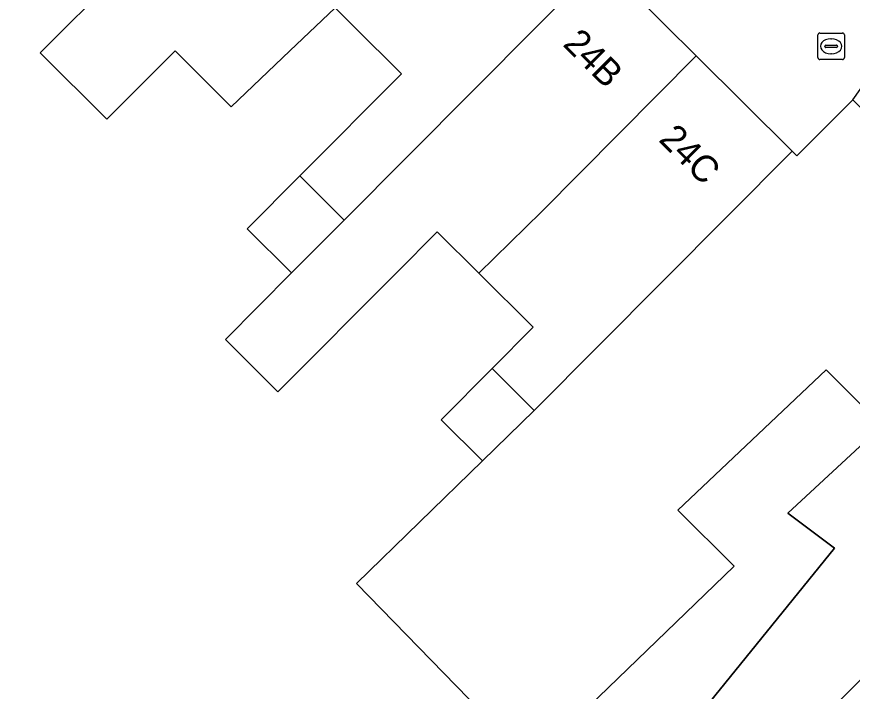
# Model space of a CAD drawing. Extents: x 160102 to 160934, y 382045 to 382923.
# Drawn here: x 160735.02 to 160766.51, y 382716.72 to 382742.13 of the extents above; entities that cross this region are included whole.
import ezdxf

# ---------------------------------------------------------------- set-up
doc = ezdxf.new("R2010")
doc.units = 0
for name, color, linetype in [('IMGEO_Brandkraan', 7, 'Continuous'), ('IMGEO_Erf', 7, 'Continuous'), ('IMGEO_Pand', 7, 'Continuous'), ('IMGEO_Pand_nummerreeks', 7, 'Continuous'), ('IMGEO_Voetpad_open', 7, 'Continuous')]:
    doc.layers.add(name, color=color, linetype=linetype)

msp = doc.modelspace()

# ---------------------------------------------------------------- linework, layer by layer
at = {"layer": 'IMGEO_Brandkraan'}
for p, q in [((160765.209, 382740.594), (160765.209, 382741.446)), ((160765.284, 382741.52), (160766.136, 382741.52)), ((160766.21, 382741.446), (160766.21, 382740.594)), ((160765.468, 382741.014), (160765.468, 382741.026)), ((160765.511, 382741.063), (160765.909, 382741.063)), ((160765.697, 382741.3), (160765.722, 382741.3)), ((160765.952, 382741.026), (160765.952, 382741.014)), ((160765.906, 382740.977), (160765.508, 382740.977)), ((160765.72, 382740.74), (160765.695, 382740.74)), ((160766.136, 382740.52), (160765.284, 382740.52))]:
    msp.add_line(p, q, dxfattribs=at)
for points in [[(160765.209, 382740.594), (160765.209, 382741.446)], [(160765.284, 382741.52), (160766.136, 382741.52)], [(160766.21, 382741.446), (160766.21, 382740.594)], [(160766.136, 382740.52), (160765.284, 382740.52)]]:
    msp.add_lwpolyline(points, dxfattribs=at)
for centre, radius, start, end in [((160765.286, 382741.444), 0.0765, 91.552, 178.448), ((160765.286, 382741.444), 0.0765, 91.552, 178.448), ((160766.134, 382741.444), 0.0765, 1.552, 88.448), ((160766.134, 382741.444), 0.0765, 1.552, 88.448), ((160765.508, 382741.023), 0.0403, 85.8775, 175.7526), ((160765.505, 382741.013), 0.0366, 178.938, 274.7102), ((160765.909, 382741.02), 0.043, 264.8664, 352.4533), ((160765.913, 382741.025), 0.0386, 1.7309, 96.639), ((160765.286, 382740.596), 0.0765, 181.552, 268.448), ((160765.286, 382740.596), 0.0765, 181.552, 268.448), ((160766.134, 382740.596), 0.0765, 271.552, 358.448), ((160766.134, 382740.596), 0.0765, 271.552, 358.448)]:
    msp.add_arc(centre, radius, start, end, dxfattribs=at)
for centre, major_axis, ratio, start_param, end_param in [((160765.696, 382741.02), (-0.387, 0.002), 0.722429, 4.712389, 7.853982), ((160765.721, 382741.02), (-0.39, 0.002), 0.717154, 1.570796, 4.712389)]:
    msp.add_ellipse(centre, major_axis=major_axis, ratio=ratio, start_param=start_param, end_param=end_param, dxfattribs=at)
at = {"layer": 'IMGEO_Erf'}
for points in [[(160766.833, 382727.519), (160765.518, 382728.827), (160759.935, 382723.549), (160762.058, 382721.439), (160754.39, 382714.036), (160747.829, 382720.785), (160752.573, 382725.396), (160751.016, 382726.944), (160752.936, 382728.875), (160754.485, 382730.433), (160752.43, 382732.476), (160750.863, 382734.034), (160749.339, 382732.501), (160744.865, 382728.001), (160742.882, 382729.973), (160745.38, 382732.486), (160743.709, 382734.148), (160745.685, 382736.134), (160749.515, 382739.985), (160747.712, 382741.778), (160747.021, 382742.466), (160745.317, 382740.845), (160743.099, 382738.735), (160740.986, 382740.846), (160738.411, 382738.269), (160735.909, 382740.769), (160738.781, 382743.643)], [(160760.151, 382715.087), (160765.841, 382722.115), (160764.083, 382723.432), (160767.295, 382726.41)]]:
    msp.add_lwpolyline(points, dxfattribs=at)
at = {"layer": 'IMGEO_Pand'}
for points in [[(160753.027, 382748.178), (160751.2, 382750), (160748.394, 382752.797), (160745.605, 382750), (160739.024, 382743.401), (160738.781, 382743.643), (160735.909, 382740.769), (160738.411, 382738.269), (160740.986, 382740.846), (160743.099, 382738.735), (160745.317, 382740.845), (160747.021, 382742.466), (160749.404, 382744.733)], [(160757.044, 382744.217), (160753.57, 382747.67), (160753.027, 382748.178), (160749.404, 382744.733), (160747.021, 382742.466), (160747.712, 382741.778), (160749.515, 382739.985), (160745.685, 382736.134), (160747.356, 382734.473)], [(160760.626, 382740.655), (160757.044, 382744.217), (160747.356, 382734.473), (160745.38, 382732.486), (160742.882, 382729.973), (160744.865, 382728.001), (160749.339, 382732.501), (160750.863, 382734.034), (160752.43, 382732.476), (160754.791, 382734.788)], [(160760.626, 382740.655), (160754.791, 382734.788), (160752.43, 382732.476), (160754.485, 382730.433), (160752.936, 382728.875), (160754.525, 382727.294), (160764.24, 382737.062)], [(160765.518, 382728.827), (160766.833, 382727.519), (160768.898, 382729.596), (160772.42, 382733.035), (160766.524, 382739.006), (160764.417, 382736.886), (160764.24, 382737.062), (160754.525, 382727.294), (160752.573, 382725.396), (160747.829, 382720.785), (160754.39, 382714.036), (160762.058, 382721.439), (160759.935, 382723.549)], [(160747.356, 382734.473), (160745.685, 382736.134), (160743.709, 382734.148), (160745.38, 382732.486)], [(160777.507, 382727.789), (160773.112, 382732.203), (160769.641, 382728.746), (160767.295, 382726.41), (160764.083, 382723.432), (160765.841, 382722.115), (160760.151, 382715.087), (160763.224, 382713.568), (160765.325, 382715.66)], [(160754.525, 382727.294), (160752.936, 382728.875), (160751.016, 382726.944), (160752.573, 382725.396)], [(160781.87, 382723.407), (160777.507, 382727.789), (160765.325, 382715.66), (160767.538, 382713.437), (160773.877, 382719.748), (160776.027, 382717.589)]]:
    msp.add_lwpolyline(points, close=True, dxfattribs=at)
at = {"layer": 'IMGEO_Voetpad_open'}
msp.add_lwpolyline([(160730.484, 382770.654), (160736.347, 382764.808), (160740.92, 382760.249), (160744.034, 382757.144), (160748.394, 382752.797), (160751.2, 382750), (160753.027, 382748.178), (160753.57, 382747.67), (160757.044, 382744.217), (160760.626, 382740.655), (160764.24, 382737.062), (160764.417, 382736.886), (160766.524, 382739.006), (160767.45, 382740.297), (160767.197, 382741.541)], dxfattribs=at)

# ---------------------------------------------------------------- texts
at = {"layer": 'IMGEO_Pand_nummerreeks'}
for s, rotation, p in [('24B', 315.1775, (160755.56, 382741.065)), ('24C', 315.1669, (160759.176, 382737.471))]:
    msp.add_text(s, height=1, rotation=rotation, dxfattribs=at).set_placement(p)

doc.saveas('drawing.dxf')
